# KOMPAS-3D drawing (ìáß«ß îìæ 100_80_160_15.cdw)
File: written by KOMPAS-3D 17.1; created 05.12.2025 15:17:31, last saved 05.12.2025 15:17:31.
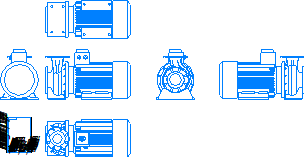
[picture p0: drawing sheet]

Sheet 1: A4, portrait

Title block, sheet 1: name: Насос МНС / 100_80_160_15; material: Сталь 10  ГОСТ 1050-88; mass: 309,93; sheets: 1; sheet format: A4

Views: Вид 1, Спереди, Проекционный вид 2, Проекционный вид 3, Проекционный вид 4, Проекционный вид 5, Проекционный вид 6
Referenced files in \\adlc.lan\data\АДЛ_ПКД\3D-модели\ADL production\Насосы ГРАНПАМП\Насосы ГРАНПАМП серии МНС\KOMPAS 3D\: Насос МНС 100-80-160_15.m3d
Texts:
  Andrey
  АДЛ
Dimensions and other numbers on the sheet: 1:1; 1; 100_80_160_15; 309,93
